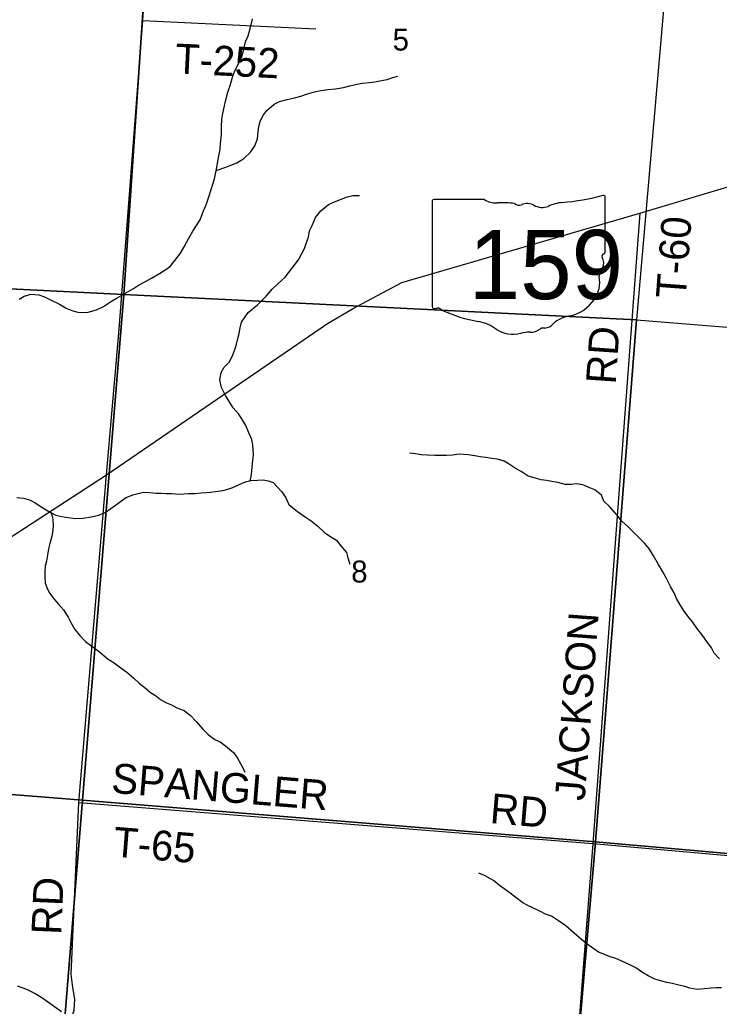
# Model space of a CAD drawing. Extents: x 1643459 to 2064572, y 425441 to 780708.
# Drawn here: x 1875648 to 1882681, y 555768 to 565687 of the extents above; entities that cross this region are included whole.
import ezdxf

# ---------------------------------------------------------------- set-up
doc = ezdxf.new("R2010")
doc.units = 0
for name, color, linetype in [('GM_X_Adjacent_County', 7, 'Continuous'), ('GM_X_Major_River', 7, 'Continuous'), ('GM_X_Major_River_Text', 7, 'Continuous'), ('GM_X_State_Route', 7, 'Continuous'), ('GM_X_US_Route', 7, 'Continuous'), ('PM_P_Cells', 7, 'Continuous'), ('RD_X_Text', 7, 'Continuous'), ('ST_Details', 7, 'Continuous')]:
    doc.layers.add(name, color=color, linetype=linetype)

msp = doc.modelspace()

# ---------------------------------------------------------------- linework, layer by layer
at = {"layer": 'GM_X_Major_River_Text'}
for points in [[(1876520.6, 561110.6), (1876648.6, 562574.4), (1876884, 565679.4), (1877076.4, 568500.6)], [(1876884, 565679.4), (1878625.5, 565596.3)], [(1881881.5, 563742.7), (1881652, 560652), (1881652, 560652)], [(1876166.2, 555642.5), (1876166.2, 555642.5), (1876193.9, 555728.3), (1876203.1, 555839), (1876182, 555956.1), (1876166.2, 556089.2), (1876241.1, 557815.9), (1876520.6, 561110.6)], [(1881652, 560652), (1881410.8, 557404.1)], [(1876241.1, 557815.9), (1881410.8, 557404.1), (1886774.6, 556930.2), (1892014.7, 556495.8)], [(1881410.8, 557404.1), (1880994.7, 552055.9)]]:
    msp.add_lwpolyline(points, dxfattribs=at)
at = {"layer": 'GM_X_State_Route'}
for points in [[(1876329.1, 568549.4), (1877070.6, 568491.1), (1876694.2, 562924.6), (1871378.8, 563190.9), (1871418.6, 563716.8), (1871776.4, 568887.9)], [(1881722.9, 568110.6), (1882318.1, 568061.3), (1881849.6, 562668.9), (1876694.2, 562924.6), (1877070.6, 568491.1)], [(1876694.2, 562924.6), (1876278.6, 557841.7), (1871007.8, 558261.9), (1871012.3, 558405.9), (1871378.8, 563190.9)], [(1881849.6, 562668.9), (1881435.5, 557421.9), (1876278.6, 557841.7), (1876694.2, 562924.6)], [(1887146.5, 562240.7), (1886800.3, 556947.5), (1881435.5, 557421.9), (1881849.6, 562668.9)], [(1871007.8, 558261.9), (1876278.6, 557841.7), (1875833.7, 552346.9), (1870578.4, 552653), (1870601.6, 552995)], [(1876278.6, 557841.7), (1881435.5, 557421.9), (1880979, 552071.2), (1875833.7, 552346.9)], [(1881435.5, 557421.9), (1886800.3, 556947.5), (1886335.9, 551626.7), (1880979, 552071.2)]]:
    msp.add_lwpolyline(points, close=True, dxfattribs=at)
at = {"layer": 'GM_X_US_Route'}
for points in [[(1875640.6, 562877.5), (1875693.2, 562909.2), (1875759.9, 562928.8), (1875838.6, 562922.2), (1875895.1, 562899.8), (1875957.7, 562869.2), (1876048.5, 562828.4), (1876115, 562787.9), (1876181.6, 562761.3), (1876232.1, 562746.9), (1876282.6, 562742.5), (1876337.1, 562746.1), (1876418, 562769.6), (1876490.8, 562803.2), (1876571.7, 562858.8), (1876628.3, 562890.5), (1876721.3, 562943.9), (1876790.1, 562983.5), (1876840.6, 563017.3), (1876913.4, 563054.9), (1876974.1, 563088.5), (1877053, 563134.1), (1877158.1, 563201.5), (1877208.8, 563265.4), (1877263.5, 563341.2), (1877302, 563405.1), (1877346.6, 563491), (1877389.2, 563560.9), (1877462.1, 563676.7), (1877494.7, 563766.8), (1877521, 563826.8), (1877545.4, 563896.8), (1877571.9, 563980.8), (1877590.2, 564032.9), (1877604.4, 564086.9), (1877618.7, 564151), (1877628.9, 564203.1), (1877649.4, 564319.3), (1877661.6, 564387.4), (1877665.8, 564443.5), (1877676.1, 564529.7), (1877676.2, 564607.9), (1877680.5, 564692.1), (1877688.6, 564744.2), (1877707, 564820.3), (1877721.2, 564880.4), (1877741.6, 564958.5), (1877762, 565024.5), (1877790.4, 565120.6), (1877810.8, 565174.6), (1877841.2, 565230.6), (1877879.7, 565318.5), (1877902.1, 565386.6), (1877918.4, 565464.7), (1877944.8, 565526.7), (1877973.3, 565636.8), (1877987.6, 565694.9)], [(1877622.6, 564170.8), (1877719.8, 564206.4), (1877770.3, 564226.1), (1877831, 564247.8), (1877899.7, 564291.4), (1877972.6, 564359), (1878013.1, 564420.9), (1878039.5, 564491), (1878045.8, 564563.1), (1878051.9, 564613.2), (1878064.1, 564663.3), (1878090.5, 564719.3), (1878133.1, 564773.1), (1878205.9, 564836.8), (1878260.5, 564864.5), (1878335.3, 564886), (1878395.9, 564899.6), (1878472.7, 564919.1), (1878541.4, 564942.7), (1878610.1, 564962.2), (1878676.8, 564975.8), (1878745.5, 564985.3), (1878822.3, 564992.8), (1878903.1, 565006.2), (1878967.8, 565021.8), (1879036.5, 565039.4), (1879095.1, 565049), (1879163.8, 565056.5), (1879218.3, 565064.1), (1879268.8, 565071.8), (1879341.6, 565087.3), (1879400.2, 565104.9), (1879450.7, 565120.6)], [(1877959.8, 561050.9), (1877967.5, 561061.4), (1877977.7, 561113.5), (1877983.9, 561189.7), (1877992.2, 561257.8), (1877998.3, 561311.9), (1877996.4, 561364.1), (1877990.5, 561414.3), (1877980.5, 561466.5), (1877952.4, 561534.9), (1877920.2, 561607.4), (1877882, 561675.9), (1877845.7, 561726.3), (1877795.4, 561784.8), (1877759.1, 561839.2), (1877716.9, 561909.7), (1877676.6, 561990.2), (1877658.6, 562066.6), (1877672.9, 562140.7), (1877703.3, 562192.7), (1877758, 562248.4), (1877790.5, 562318.4), (1877818.9, 562398.4), (1877839.3, 562480.5), (1877855.6, 562532.5), (1877863.8, 562590.7), (1877878, 562646.7), (1877944.9, 562744.5), (1878038, 562820.1), (1878125, 562907.7), (1878185.7, 562977.5), (1878242.4, 563033.2), (1878317.3, 563098.9), (1878451, 563274.4), (1878483.4, 563336.4), (1878509.8, 563388.3), (1878530.1, 563448.4), (1878550.4, 563502.4), (1878560.7, 563564.5), (1878587.1, 563618.5), (1878621.6, 563698.4), (1878676.2, 563766.2), (1878751.1, 563829.9), (1878811.8, 563857.5), (1878872.4, 563881.2), (1878931, 563904.8), (1878997.7, 563920.4), (1879064.4, 563919.9)], [(1882682, 559260.2), (1882631.6, 559316.7), (1882603.4, 559371.1), (1882557.1, 559435.6), (1882516.8, 559492.1), (1882456.4, 559568.7), (1882412.1, 559633.2), (1882365.8, 559689.7), (1882329.5, 559740.1), (1882289.3, 559802.6), (1882251, 559869.1), (1882226.9, 559923.4), (1882190.7, 559987.9), (1882146.4, 560076.4), (1882114.3, 560136.8), (1882072, 560211.4), (1882021.7, 560296), (1881979.4, 560362.5), (1881933.1, 560421), (1881868.6, 560483.6), (1881818.2, 560536.2), (1881763.8, 560588.7), (1881701.3, 560645.3), (1881650.9, 560707.9), (1881576.4, 560792.6), (1881521.9, 560847.2), (1881495.8, 560905.5), (1881429.3, 560960.2), (1881362.7, 560988.8), (1881310.2, 561009.2), (1881249.6, 561019.7), (1881191.1, 561014.1), (1881132.5, 561014.5), (1881059.8, 561033.1), (1880999.2, 561045.5), (1880944.7, 561056), (1880892.2, 561062.4), (1880821.6, 561080.9), (1880761, 561097.4), (1880690.4, 561146.1), (1880640, 561172.5), (1880569.4, 561217.1), (1880519, 561247.6), (1880452.3, 561268.1), (1880395.8, 561274.5), (1880333.2, 561285), (1880276.7, 561293.5), (1880222.2, 561301.9), (1880157.5, 561312.4), (1880066.7, 561319.1), (1879998, 561309.5), (1879939.4, 561305.9), (1879880.8, 561304.4), (1879820.2, 561304.8), (1879747.5, 561309.3), (1879682.9, 561313.8), (1879626.3, 561322.2), (1879565.8, 561330.7)], [(1875620.1, 560881.8), (1875688.8, 560875.3), (1875753.3, 560856.8), (1875803.8, 560830.4), (1875870.3, 560785.8), (1875930.8, 560749.2), (1876009.5, 560706.5), (1876070.1, 560692), (1876156.9, 560677.4), (1876207.4, 560673), (1876284.2, 560674.4), (1876369, 560689.9), (1876441.8, 560707.4), (1876506.5, 560733), (1876565.1, 560772.7), (1876633.9, 560822.4), (1876712.8, 560880), (1876783.6, 560909.5), (1876840.2, 560925.2), (1876896.7, 560936.8), (1876957.3, 560934.3), (1877017.9, 560927.9), (1877068.4, 560925.5), (1877120.9, 560923.1), (1877175.4, 560922.8), (1877250.2, 560918.2), (1877345.1, 560923.5), (1877413.8, 560925), (1877472.4, 560930.6), (1877565.3, 560936), (1877615.8, 560943.6), (1877688.5, 560955.2), (1877739.1, 560968.8), (1877789.6, 560984.5), (1877854.3, 561014.1), (1877917, 561041.8), (1877971.5, 561053.4), (1878038.2, 561058.9), (1878094.7, 561060.5), (1878145.2, 561052.1), (1878195.7, 561033.7), (1878278.3, 560942.9), (1878320.6, 560886.4), (1878352.7, 560811.9), (1878441.5, 560741.1), (1878508, 560694.5), (1878576.6, 560649.8), (1878645.2, 560595.2), (1878711.7, 560530.5), (1878764.1, 560494), (1878832.7, 560453.4)], [(1875960.4, 560733.2), (1875977.2, 560690.7), (1875985.1, 560608.4), (1875978.9, 560552.3), (1875970.7, 560494.2), (1875950.3, 560420.1), (1875938.1, 560368), (1875925.8, 560304), (1875915.6, 560243.8), (1875903.4, 560191.8), (1875899.2, 560141.7), (1875899.1, 560085.5), (1875905.1, 560025.3), (1875925.1, 559967), (1875949.2, 559916.7), (1875991.5, 559864.2), (1876037.9, 559811.7), (1876088.3, 559753.2), (1876134.6, 559680.6), (1876162.7, 559626.3), (1876200.9, 559555.8), (1876251.3, 559497.2), (1876307.7, 559434.7), (1876374.3, 559390), (1876432.8, 559345.5), (1876537.6, 559256.5), (1876598.1, 559221.9), (1876662.6, 559171.3), (1876723.1, 559126.8), (1876793.7, 559068.1), (1876848.1, 559017.5), (1876910.6, 558966.9), (1876961, 558922.4), (1877013.5, 558892), (1877063.9, 558851.5), (1877122.4, 558819), (1877174.9, 558798.5), (1877227.3, 558770.1), (1877300, 558741.5), (1877364.5, 558690.9), (1877422.9, 558632.3), (1877489.4, 558555.6), (1877543.8, 558501), (1877610.4, 558450.4), (1877662.9, 558425.9), (1877715.3, 558387.5), (1877795.9, 558318.7), (1877836.2, 558262.2), (1877886.5, 558173.6), (1877910.6, 558121.3)], [(1878832.7, 560453.4), (1878877, 560398.9), (1878933.4, 560330.3), (1878947.4, 560276.1), (1878965.5, 560213.8)], [(1882703.1, 555954.4), (1882650.6, 555954.8), (1882598.1, 555951.2), (1882531.4, 555941.7), (1882460.7, 555936.2), (1882386, 555950.7), (1882333.5, 555965.2), (1882262.8, 555983.7), (1882206.3, 555998.2), (1882155.8, 556008.6), (1882103.3, 556019), (1882034.7, 556039.5), (1881968.1, 556074.1), (1881909.6, 556108.6), (1881843.1, 556153.2), (1881788.6, 556181.7), (1881726.1, 556212.2), (1881641.3, 556247), (1881582.7, 556265.4), (1881526.2, 556289.9), (1881465.7, 556312.4), (1881397.1, 556363.1), (1881340.7, 556401.6), (1881272.1, 556458.2), (1881221.7, 556504.7), (1881139.1, 556577.5), (1881064.4, 556628.2), (1880993.8, 556672.9), (1880935.3, 556695.3), (1880882.8, 556719.8), (1880808.2, 556756.4), (1880755.7, 556780.9), (1880705.3, 556807.3), (1880636.7, 556860), (1880564.1, 556914.7), (1880471.4, 556981.5), (1880410.9, 557032.1), (1880322.1, 557082.9), (1880263.6, 557107.4)]]:
    msp.add_lwpolyline(points, dxfattribs=at)
at = {"layer": 'RD_X_Text'}
for points in [[(1853657.5, 538646.9), (1857824, 545139), (1858024.6, 545446.5), (1859783.8, 548105.1), (1860677.2, 549070.2), (1862259.5, 550763.3), (1863222.8, 551834.8), (1863365.3, 551990.7), (1867521.9, 555002.8), (1870936.5, 557440), (1872281.9, 558357.7), (1876520.6, 561110.6), (1878743.2, 562632), (1878992.9, 562780.9), (1879491.3, 563043.6), (1881881.5, 563742.7), (1885154.4, 564722.2), (1885647.9, 564774.5), (1886515.6, 564866.4), (1886707.8, 564902.4), (1886849.8, 564972.7), (1887257.5, 565263.8), (1887306.4, 565298.7)], [(1875621, 555973.5), (1875715.2, 555938.9), (1875804.2, 555896), (1875879.6, 555849.9), (1876067.6, 555716.1)]]:
    msp.add_lwpolyline(points, dxfattribs=at)
at = {"layer": 'ST_Details'}
for p, q in [((1881534.8, 563351.7), (1881534.8, 563904.5)), ((1879794.6, 563860.1), (1879794.6, 562803.5)), ((1880321.4, 563878.3), (1879811.8, 563878.3)), ((1881534.7, 563351.9), (1881534.8, 563351.7))]:
    msp.add_line(p, q, dxfattribs=at)
for centre, major_axis, start_param, end_param in [((1880914.9, 565318.8), (1845.5, 0), 4.814394, 5.042369), ((1881515.5, 563906.8), (19.4, 0), 6.141152, 7.989035), ((1879814.6, 563862.3), (20.2, 0), 1.712693, 3.28349), ((1880442.8, 564000.9), (195.5, 0), 4.042523, 4.731795), ((1880507.6, 563285.1), (702, 0), 1.404758, 1.657858), ((1880667, 563867.8), (56.4, 0), 3.836095, 5.185415), ((1880749.8, 563745.7), (117.3, 0), 0.950623, 2.079405), ((1880901.2, 563913.2), (141.1, 0), 4.081561, 5.145723), ((1881150.3, 563555.5), (371.3, 0), 1.699011, 2.107814), ((1881530.4, 563311.1), (30, 0), 1.883978, 3.671073), ((1881514.2, 563349.6), (20.7, 0), 5.05454, 6.418171), ((1881339.6, 563241.3), (180, 0), 5.934695, 6.695948), ((1881018.3, 563050.1), (461.6, 0), 5.101752, 6.440018), ((1881604.2, 563120.4), (130.9, 0), 2.387724, 3.262537), ((1879814.7, 562801.1), (20.3, 0), 3.00124, 4.508301), ((1879817.8, 562909.2), (155.2, 0), 4.665946, 4.897461), ((1879849.6, 562742.5), (56, 0), 0.519207, 1.627899), ((1880556.2, 563691.8), (1332.7, 0), 4.195997, 4.488961), ((1880158.9, 562328.8), (417, 0), 0.823519, 1.323587), ((1880892.7, 562701), (149.1, 0), 4.937069, 5.64225), ((1881213, 562506.8), (252.8, 0), 1.647645, 2.488434), ((1880609.8, 562737.3), (264.6, 0), 4.026481, 4.996735), ((1880762.7, 562371.9), (217.4, 0), 1.495662, 1.94098), ((1880782, 562658.1), (141, 0), 4.691044, 5.507374), ((1880909.6, 562555.8), (39.7, 0), 1.147584, 2.315152)]:
    msp.add_ellipse(centre, major_axis=major_axis, ratio=0.8, start_param=start_param, end_param=end_param, dxfattribs=at)

# ---------------------------------------------------------------- texts
at = {"layer": 'GM_X_Adjacent_County'}
for s, p in [('5', (1879396.8, 565377.2)), ('8', (1878981, 560028.4))]:
    msp.add_text(s, height=221, rotation=0.00001, dxfattribs=at).set_placement(p)
at = {"layer": 'GM_X_Major_River'}
for s, rotation, p in [('T-252', 357.19408, (1877204.3, 565148.8)), ('T-60', 85.7632, (1882342.6, 562876)), ('RD', 86.02095, (1881639.7, 562016.3)), ('JACKSON', 85.71846, (1881327.3, 557828.1)), ('SPANGLER', 355.34667, (1876561.7, 557914.9)), ('RD', 355.07376, (1880368.3, 557611.2)), ('T-65', 355.38346, (1876580.7, 557273.9)), ('RD', 87.53133, (1876064.7, 556482.4))]:
    msp.add_text(s, height=300, rotation=rotation, dxfattribs=at).set_placement(p)
at = {"layer": 'PM_P_Cells'}
for s in ['s', 'r']:
    msp.add_text(s, height=1, dxfattribs=at).set_placement((1880645.2, 563261.5))
msp.add_text('159', height=1, rotation=0.00001, dxfattribs=at).set_placement((1880292.2, 563188.8))
at = {"layer": 'ST_Details'}
msp.add_text('159', height=696.1, dxfattribs=at).set_placement((1880161.5, 562878))

doc.saveas('drawing.dxf')
